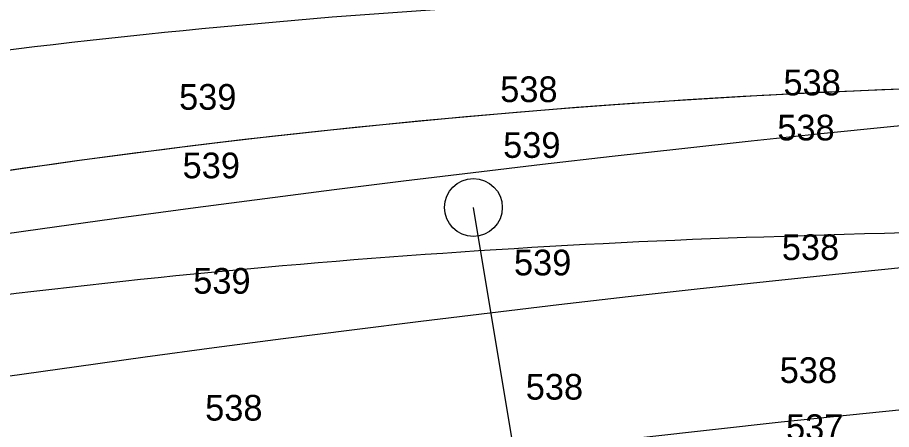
# Model space of a CAD drawing. Extents: x 1787461 to 1970323, y 938412 to 1118748.
# Drawn here: x 1967999.8 to 1968067.8, y 1117913.9 to 1117945.9 of the extents above; entities that cross this region are included whole.
import ezdxf

# ---------------------------------------------------------------- set-up
doc = ezdxf.new("R2010")
doc.units = 0
for name, color, linetype in [('Default', 7, 'Continuous'), ('HHA ADDITIONAL XSs', 7, 'Continuous'), ('Level 19', 7, 'Continuous'), ('RD_EX_DV_Prop', 7, 'Continuous'), ('RD_EX_Road', 7, 'Continuous'), ('RD_HC_CL', 7, 'Continuous'), ('RD_HC_CL_Rel', 7, 'Continuous'), ('RD_PD_Final_TrvlWay', 7, 'Continuous')]:
    doc.layers.add(name, color=color, linetype=linetype)

msp = doc.modelspace()

# ---------------------------------------------------------------- linework, layer by layer
at = {"layer": 'HHA ADDITIONAL XSs'}
msp.add_arc((1968231.344, 1116297.536), 1667.022, 87.726628, 111.995838, dxfattribs=at)
at = {"layer": 'Level 19'}
msp.add_line((1968039.901, 1117903.631), (1968035.295, 1117931.147), dxfattribs=at)
msp.add_circle((1968035.295, 1117931.147), 2.25, dxfattribs=at)
at = {"layer": 'RD_EX_DV_Prop'}
msp.add_arc((1968093.163, 1117286.891), 653.927, 87.726629, 109.21172, dxfattribs=at)
at = {"layer": 'RD_EX_Road'}
for centre, radius, start, end in [((1968073.854, 1117330.008), 617.928, 91.496487, 100.129532), ((1968106.327, 1116513.625), 1416.047, 87.911481, 91.959758), ((1968079.486, 1117255.881), 673.309, 91.837024, 99.405709)]:
    msp.add_arc(centre, radius, start, end, dxfattribs=at)
at = {"layer": 'RD_HC_CL'}
msp.add_arc((1968093.163, 1117286.891), 653.927, 87.726628, 111.995838, dxfattribs=at)
at = {"layer": 'RD_HC_CL_Rel'}
msp.add_arc((1968231.344, 1116297.536), 1637.022, 87.726628, 111.995838, dxfattribs=at)
at = {"layer": 'RD_PD_Final_TrvlWay'}
for radius in [1648.022, 1626.022]:
    msp.add_arc((1968231.344, 1116297.536), radius, 87.726628, 111.995838, dxfattribs=at)

# ---------------------------------------------------------------- texts
at = {"layer": 'Default'}
for s, p in [('538', (1968037.382, 1117939.348)), ('538', (1968059.419, 1117939.872)), ('539', (1968012.392, 1117938.753)), ('538', (1968058.944, 1117936.367)), ('539', (1968037.61, 1117935.008)), ('539', (1968012.664, 1117933.418)), ('538', (1968059.295, 1117927.052)), ('539', (1968038.451, 1117925.862)), ('539', (1968013.493, 1117924.436)), ('538', (1968059.13, 1117917.486)), ('538', (1968039.367, 1117916.193)), ('538', (1968014.421, 1117914.56)), ('537', (1968059.623, 1117913.047))]:
    msp.add_text(s, height=2, dxfattribs=at).set_placement(p)

doc.saveas('drawing.dxf')
